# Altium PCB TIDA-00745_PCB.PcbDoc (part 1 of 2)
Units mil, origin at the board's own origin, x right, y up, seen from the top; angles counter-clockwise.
Board outline 7745 x 3490 mil, 4 copper layers (Top Layer, Signal Layer 1, Signal Layer 2, Bottom Layer), stack 61.2 mil thick; 181 components, 60 nets, 404 pads, 89 vias.
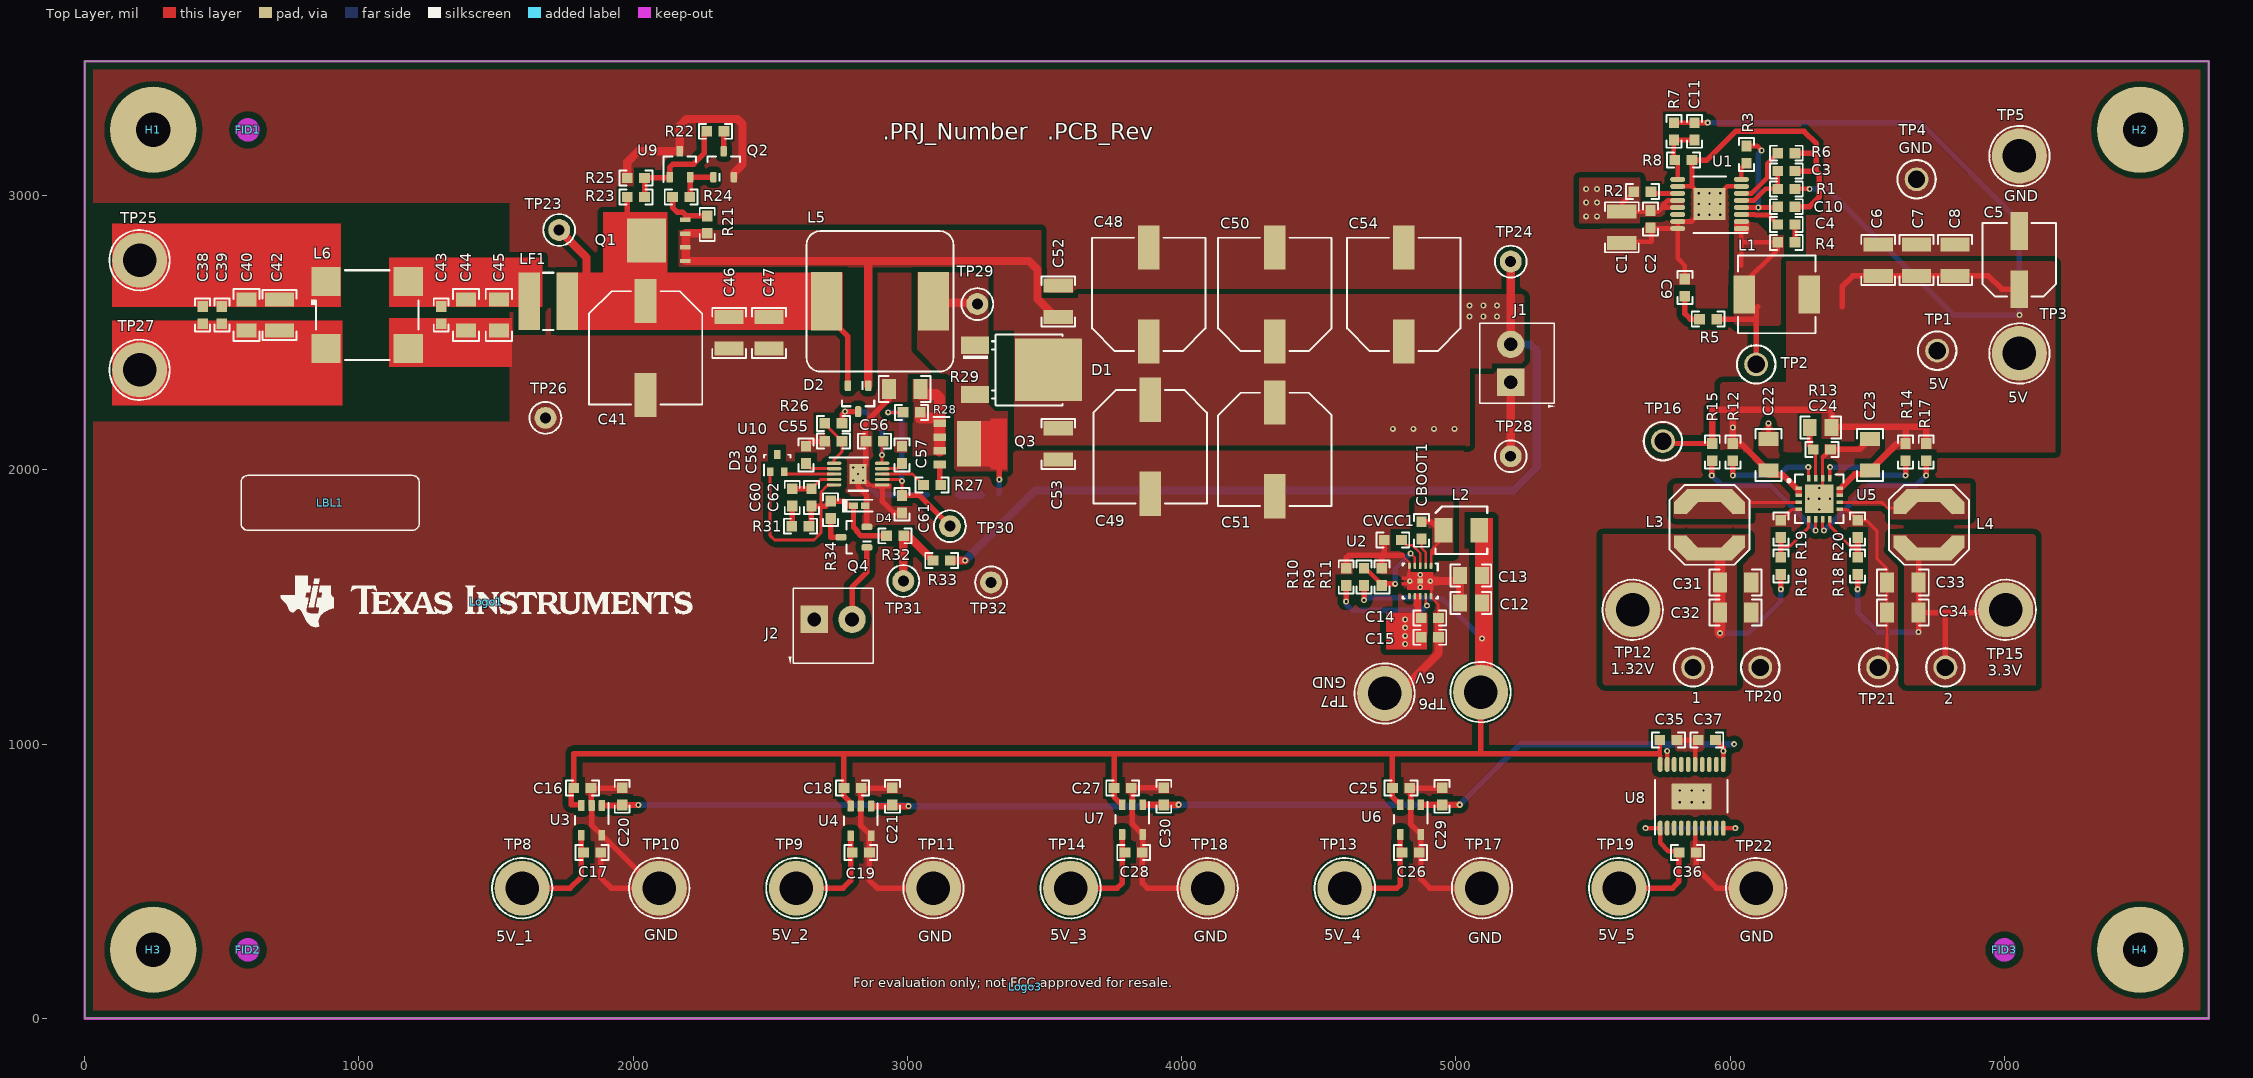
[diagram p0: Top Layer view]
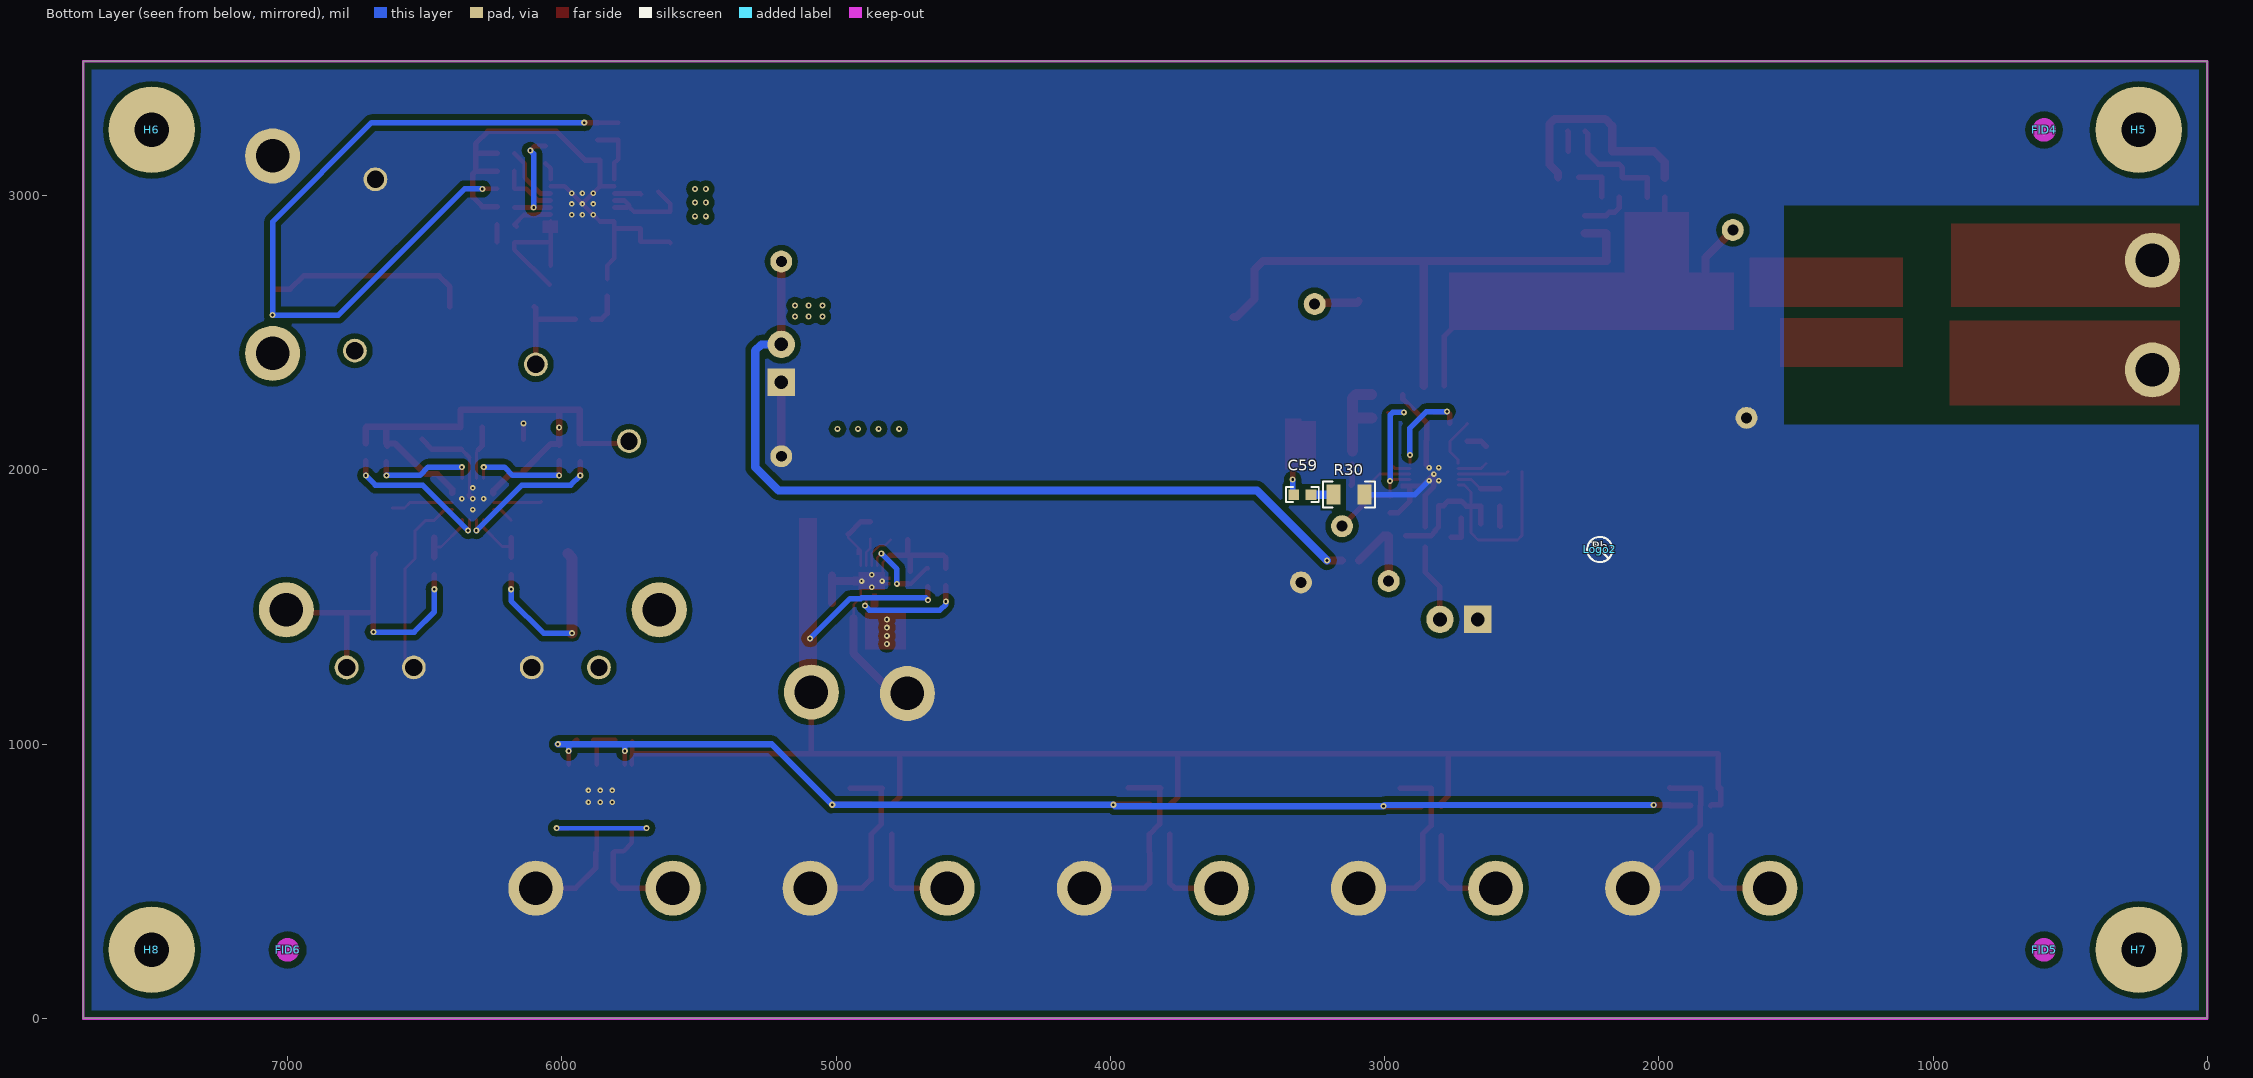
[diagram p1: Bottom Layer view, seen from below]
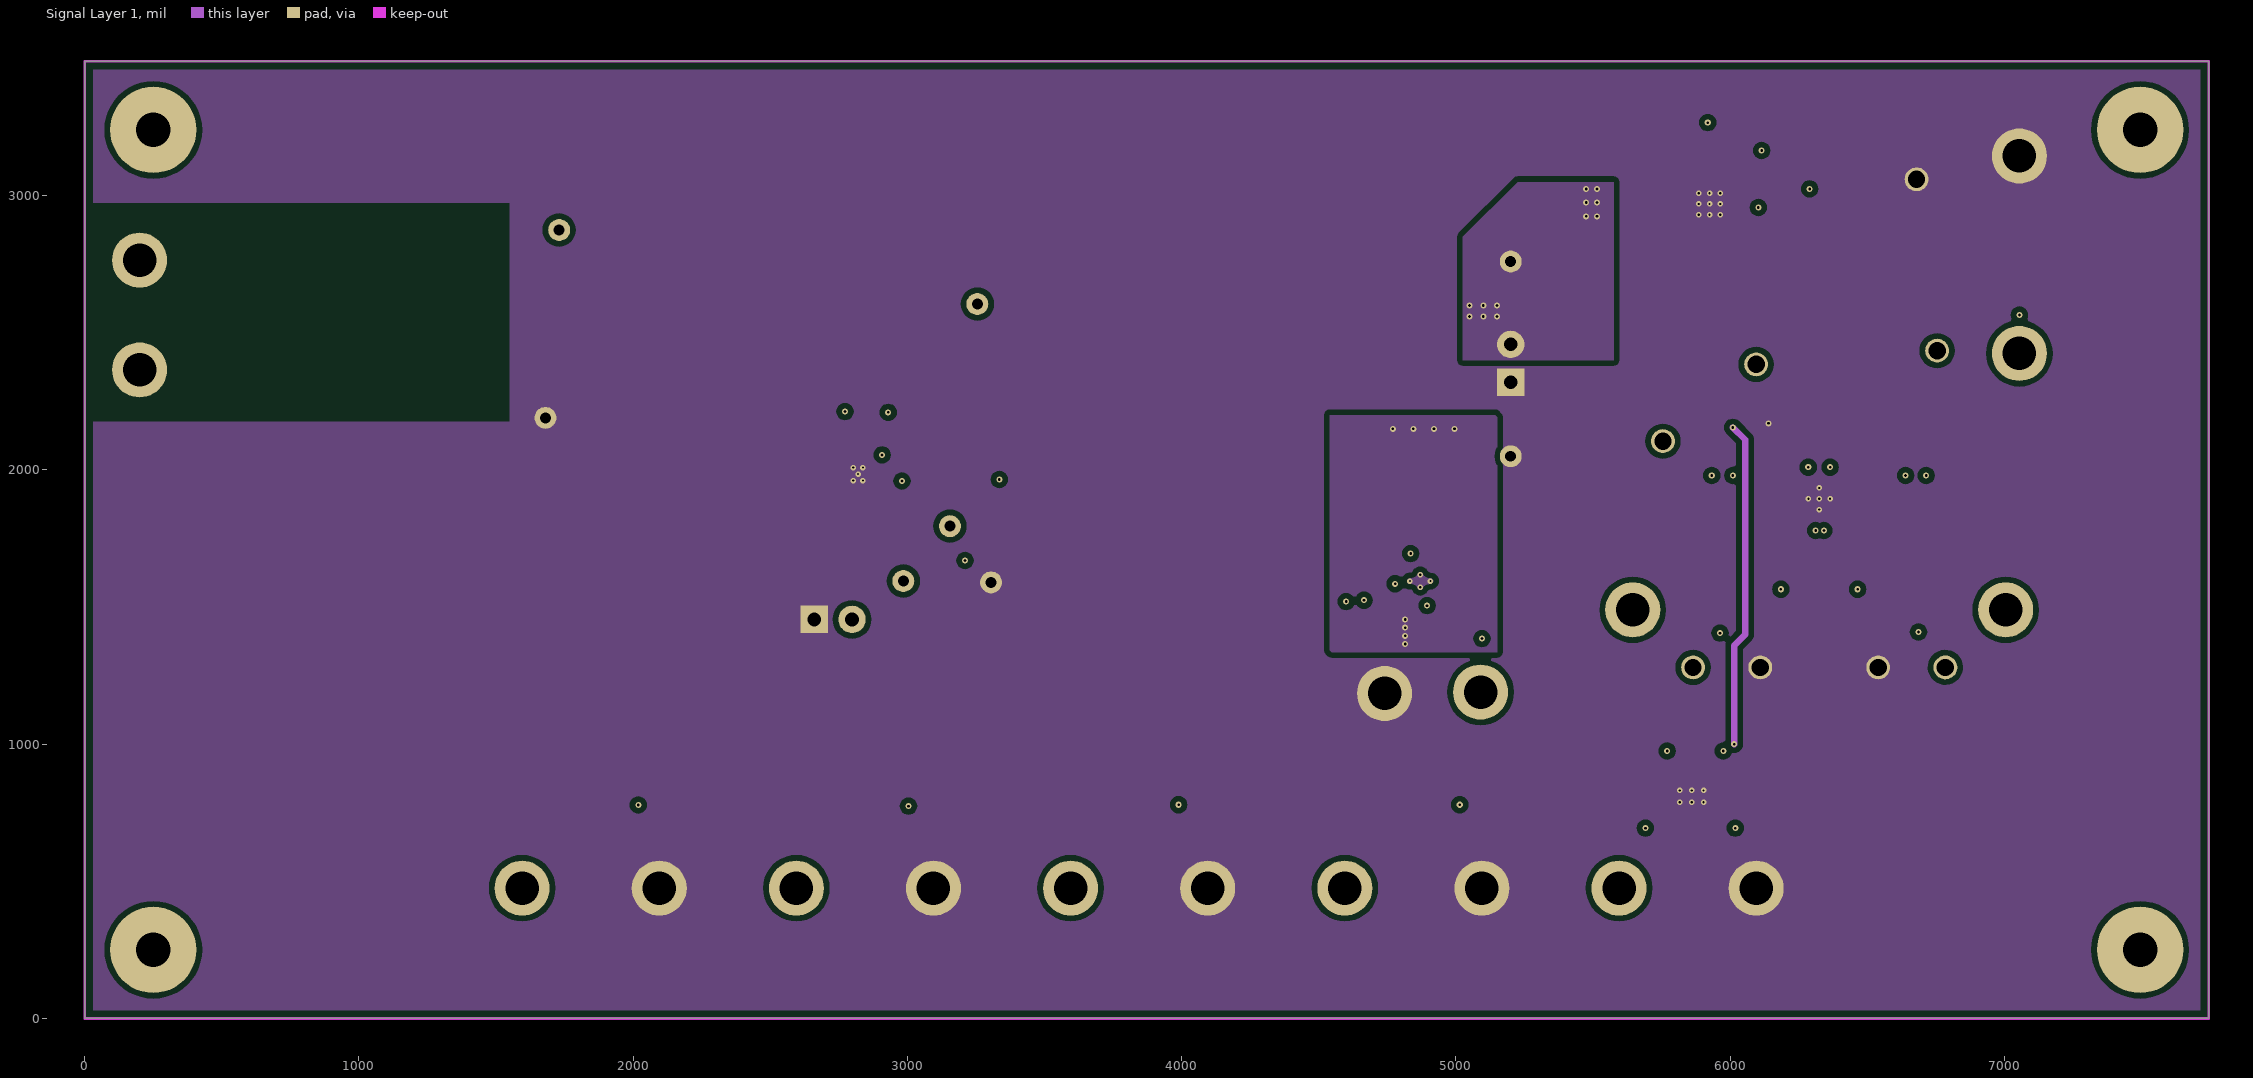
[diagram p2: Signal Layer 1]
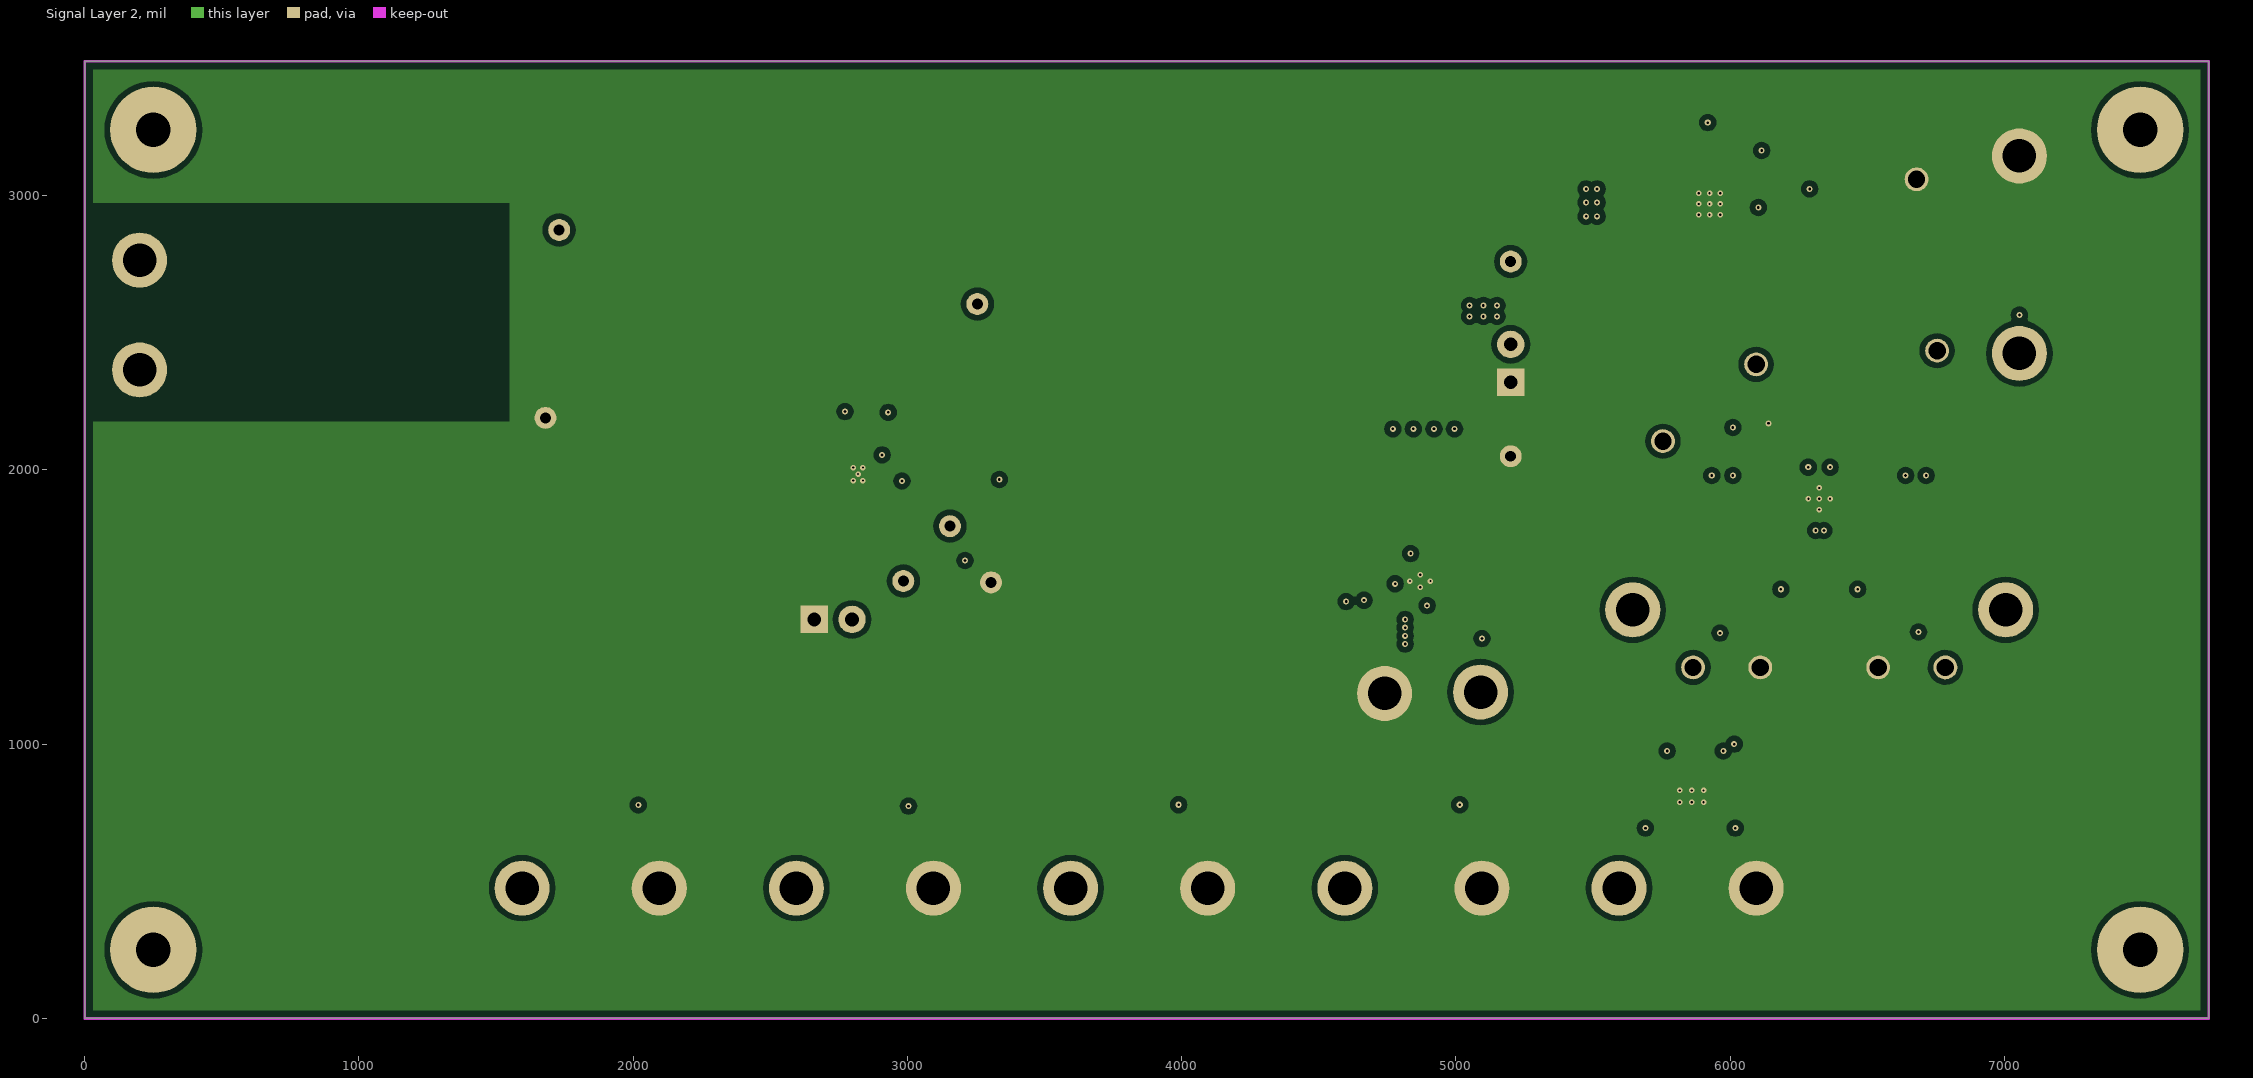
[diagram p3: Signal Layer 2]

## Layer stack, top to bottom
Top Layer: signal copper 1.4
Dielectric: core 26, FR-4, Dk 4.2
Signal Layer 1: signal copper 0.7
Dielectric: prepreg 5, Dk 4.2
Signal Layer 2: signal copper 0.7
Dielectric: core 26, Dk 4.2
Bottom Layer: signal copper 1.4

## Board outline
0,0 0,3490 7745,3490 7745,0

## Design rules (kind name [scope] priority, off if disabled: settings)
AcuteAngle [All] p1: minimum=4.50000000000000E+0001 checktracksonly=FALSE
AssemblyTestPointUsage [All] p1: valid=2
Clearance Clearance_Keepouts [((IsTrack Or IsArc) And Not InPoly) And IsFree and IsKeepOut vs ((IsTrack Or IsArc) And Not InPoly) And IsFree and IsKeepOut] p1: gap=0
Clearance Clearance_BoardEdge_MountingHoles [OnCopper and InComponentClass('Mounting Holes') vs IsKeepOut] p2: gap=40
Clearance Clearance_BoardEdge_Poly [OnCopper and InPoly vs IsKeepOut] p3: gap=25
Clearance Clearance_BoardEdge [OnCopper and Not InComponentClass('Logo') and not InComponentClass('FiducialMark') and not InRegion(1000,500,4000,800) and Not IsKeepout vs IsKeepOut] p4: gap=75
Clearance Clearance_Poly [InPolygon] p5: gap=20
Clearance [All] p6: gap=7.87
ComponentClearance ComponentClearance_MountingHoles_FiducialMarks [InComponentClass('Mounting Holes') vs InComponentClass('FiducialMark')] p1: gap=50 collisioncheckmode=3 verticalgap=10 showdistances=FALSE
ComponentClearance ComponentClearance_Shunt [InComponentClass('Header') vs InComponentClass('Shunt')] p2: gap=0 collisioncheckmode=3 verticalgap=0 showdistances=FALSE
ComponentClearance ComponentClearance_Logo [InComponentClass('Logo')] p3: gap=50 collisioncheckmode=3 verticalgap=10 showdistances=FALSE
ComponentClearance ComponentClearance_ScrewToNut [(HasFootprint('NY PMS 440 0025 PH')) vs (HasFootprint('Keystone_1902C'))] p4: gap=5 collisioncheckmode=3 verticalgap=10 showdistances=FALSE
ComponentClearance ComponentClearance_MountingHoles [InComponentClass('Mounting Holes')] p5: gap=250 collisioncheckmode=3 verticalgap=100000 showdistances=FALSE
ComponentClearance ComponentClearance_SmallPassives [HasFootprint('0201*') or HasFootprint('0402*') or HasFootprint('0508') or HasFootprint('0603*') or HasFootprint('0612') or HasFootprint('0805*') or HasFootprint('0815*') or HasFootprint('0830*') or HasFootprint('1206*') or HasFootprint('1210*') or HasFootprint('1808*') or HasFootprint('1812*') or HasFootprint('1825*') or HasFootprint('2010*') or HasFootprint('2220*') or HasFootprint('2225*') or HasFootprint('2512*') or HasFootprint('2728*') or HasFootprint('3518*') vs HasFootprint('0201*') or HasFootprint('0402*') or HasFootprint('0508') or HasFootprint('0603*') or HasFootprint('0612') or HasFootprint('0805*') or HasFootprint('0815*') or HasFootprint('0830*') or HasFootprint('1206*') or HasFootprint('1210*') or HasFootprint('1808*') or HasFootprint('1812*') or HasFootprint('1825*') or HasFootprint('2010*') or HasFootprint('2220*') or HasFootprint('2225*') or HasFootprint('2512*') or HasFootprint('2728*') or HasFootprint('3518*')] p6: gap=20 collisioncheckmode=3 verticalgap=10 showdistances=FALSE
ComponentClearance ComponentClearance_THtoSMT [IsThruComponent vs IsSMTComponent] p7: gap=100 collisioncheckmode=3 verticalgap=30 showdistances=FALSE
ComponentClearance ComponentClearance_THtoTH [IsThruComponent vs IsThruComponent] p8: gap=118.11 collisioncheckmode=3 verticalgap=30 showdistances=FALSE
ComponentClearance [All] p9: gap=40 collisioncheckmode=3 verticalgap=10 showdistances=FALSE
DiffPairsRouting [All] p1: maxlimit=100 minlimit=10 mostfreqgap=10 maxuncoupledlength=1000
FabricationTestPointUsage TestPointUsage [All] p1: valid=2 allowmultiple=FALSE
FabricationTestpoint Testpoint [All] p1: side=3 testpointundercomponent=TRUE minsize=40 maxsize=100 preferedsize=60 minholesize=0 maxholesize=40 preferedholesize=32 testpointgrid=1 allowsidetop=TRUE allowsidebottom=TRUE usegrid=TRUE gridtolerance=0.01
FanoutControl Fanout_LCC [IsLCC] p1: bgadir=Out bgaviamode=Centered fanoutstyle=Auto fanoutdirection=Alternating viagrid=1 // Fanout_LCC (Default Rule)
FanoutControl Fanout_BGA [IsBGA] p2: bgadir=Out bgaviamode=Centered fanoutstyle=Auto fanoutdirection=Alternating viagrid=1 // Fanout_BGA (Default Rule)
FanoutControl Fanout_Default [All] p4: bgadir=Out bgaviamode=Centered fanoutstyle=Auto fanoutdirection=Alternating viagrid=1 // Fanout_Default (Default Rule)
FanoutControl Fanout_Small [(CompPinCount < 5)] p5: bgadir=Out bgaviamode=Centered fanoutstyle=Auto fanoutdirection=OutThenIn viagrid=1 // Fanout_Small (Default Rule)
HoleSize [All] p1: absolutevalues=TRUE maxlimit=251 minlimit=8 maxpercent=80.000 minpercent=20.000
MinimumAnnularRing MinimumAnnularRing_ThermalPadVias [IsVia and InAnyComponent] p1: minimumring=6
MinimumAnnularRing [All] p2: minimumring=6
MinimumSolderMaskSliver MinimumSolderMaskSliver_Logo [InComponentClass('Logo') vs InComponentClass('Logo')] p1: minsoldermaskwidth=0.7
MinimumSolderMaskSliver [All] p2: minsoldermaskwidth=3.94
PlaneConnect [All] p1: planeconnectstyle=Relief reliefexpansion=10 reliefentries=4 reliefconductorwidth=10 reliefairgap=10
PolygonConnect [All] p1: connectstyle=Direct reliefconductorwidth=10 reliefentries=4 polygonreliefangle="90 Angle" airgapwidth=10
RoutingVias ThermalPadVias [IsVia and InAnyComponent] p1: holewidth=8 width=20 viastyle="Through Hole" minholewidth=8 minwidth=20 maxholewidth=12.99 maxwidth=23.62
RoutingVias [All] p2: holewidth=16 width=34 viastyle="Through Hole" minholewidth=8 minwidth=20 maxholewidth=40 maxwidth=65
SilkToSilkClearance SilkToSilkClearance_Pb-FreeLogo [(HasFootprint('Pb-Free_Overlay_Medium') OR HasFootprint('Pb-Free_Overlay_Small')) vs (HasFootprint('Pb-Free_Overlay_Medium') OR HasFootprint('Pb-Free_Overlay_Small'))] p1: silktosilkclearance=0
SilkToSilkClearance [All] p2: silktosilkclearance=4
SilkscreenOverComponentPads SilkToComonentPadClearance [IsPad and InAnycomponent] p1: minsilkscreentomaskgap=5
SilkscreenOverComponentPads "Silk to Solder Mask Opening" [All] p2: minsilkscreentomaskgap=4
SolderMaskExpansion [All] p1: expansion=1.97
Width [All] p1: maxlimit=100 minlimit=6 preferedwidth=10 checkconnectedcopper=TRUE
14 further rules are at their usual default settings.

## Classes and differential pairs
component class "TIDA-00745_Buck REV1": 1 2 C1 C2 C3 C4 C5 C6 C7 C8 C9 C10 C11 C12 C13 C14 C15 C16 C17 C18 C19 C20 C21 C22 C23 C24 C25 C26 C27 C28 C29 C30 C31 C32 C33 C34 C35 C36 C37 CBOOT1 CVCC1 L1 L2 L3 L4 R1 R2 R3 R4 R5 R6 R7 R8 R9 R10 R11 R12 R13 R14 R15 R16 R17 R18 R19 R20 TP1 TP2 TP3 TP4 TP5 TP6 TP7 TP8 TP9 TP10 TP11 TP12 TP13 TP14 TP15 TP16 TP17 TP18 TP19 TP20 TP21 TP22 U1 U2 U3 U4 U5 U6 U7 U8
component class "TIDA-00745 REV1": C38 C39 C40 C41 C42 C43 C44 C45 C46 C47 C48 C49 C50 C51 C52 C53 C54 C55 C56 C57 C58 C59 C60 C61 C62 D1 D2 D3 D4 J1 J2 L5 L6 LF1 Q1 Q2 Q3 Q4 R21 R22 R23 R24 R25 R26 R27 R28 R29 R30 R31 R32 R33 R34 TP23 TP24 TP25 TP26 TP27 TP28 TP29 TP30 TP31 TP32 U9 U10
component class Label: LBL1
component class "Mounting Holes": H1 H2 H3 H4
component class Logo: Logo1
component class TIDA-00745_Hardware: FID1 FID2 FID3 FID4 FID5 FID6 H1 H2 H3 H4 H5 H6 H7 H8 LBL1 Logo1 Logo2 Logo3 ZZ1 ZZ2 ZZ3 ZZ4
component class FiducialMark: FID1 FID2 FID3 FID4 FID5 FID6
component class AssemblyNote: ZZ1 ZZ2 ZZ3 ZZ4

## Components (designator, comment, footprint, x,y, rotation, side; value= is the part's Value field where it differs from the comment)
1 "5010" Keystone5010 5865,1280 r0 top
2 "5010" Keystone5010 6785,1280 r3 top
C1 "GRM32ER71H106KA12L" 1210 5605,2885 r270 top
C2 "06035C104KAT2A" 0603 5710,2915 r270 top
C3 "06035C104KAT2A" 0603 6205,3090 r0 top
C4 "C0603C474K8RACTU" 0603 6205,2895 r180 top
C5 "APXC6R3ARA181MF60G" CAPSMT_62_F60 7055,2765 r90 top
C6 "C3225X7R1C226M" 1210 6540,2765 r90 top
C7 "C3225X7R1C226M" 1210 6680,2765 r90 top
C8 "C3225X7R1C226M" 1210 6820,2765 r90 top
C9 "06031C102JAT2A" 0603 5835,2665 r90 top
C10 "GRM188R71A225KE15D" 0603 6205,2960 r0 top
C11 "GRM188R71E333KA01D" 0603 5870,3235 r270 top
C12 "C2012X7R1A106K125AC" 0805_HV 5055,1515 r180 top
C13 "C2012X7R1A106K125AC" 0805_HV 5055,1615 r180 top
C14 "GRM188R61C475KAAJ" 0603 4905,1460 r180 top
C15 "0603YC104JAT2A" 0603 4905,1390 r180 top
C16 "GRM188R71A105KA61D" 0603 1815,840 r0 top
C17 "GRM188R71A225KE15D" 0603 1850,605 r0 top
C18 "GRM188R71A105KA61D" 0603 2800,840 r0 top
C19 "GRM188R71A225KE15D" 0603 2830,605 r0 top
C20 "0603ZC103KAT2A" 0603 1960,810 r90 top
C21 "0603ZC103KAT2A" 0603 2945,810 r90 top
C22 "GRM31CR71A106KA01L" 1206 6140,2055 r90 top
C23 "GRM31CR71A106KA01L" 1206 6510,2055 r90 top
C24 "GRM188R71A474KA61D" 0603 6335,2075 r0 top
C25 "GRM188R71A105KA61D" 0603 4800,840 r0 top
C26 "GRM188R71A225KE15D" 0603 4835,605 r0 top
C27 "GRM188R71A105KA61D" 0603 3785,840 r0 top
C28 "GRM188R71A225KE15D" 0603 3825,605 r0 top
C29 "0603ZC103KAT2A" 0603 4950,810 r90 top
C30 "0603ZC103KAT2A" 0603 3935,810 r90 top
C31 "GRM31CR60J476ME19L" 1206 6020,1590 r0 top
C32 "GRM31CR71A226KE15L" 1206 6020,1480 r0 top
C33 "GRM31CR60J476ME19L" 1206 6630,1590 r180 top
C34 "GRM31CR71A226KE15L" 1206 6630,1480 r180 top
C35 "GRM188R71A105KA61D" 0603 5775,1015 r0 top
C36 "GRM188R71A225KE15D" 0603 5845,605 r0 top
C37 "0603ZC103KAT2A" 0603 5915,1015 r180 top
C38 "06031C102KAT2A" 0603 430,2565 r270 top
C39 "GRM188R72A104KA35D" 0603 500,2565 r270 top
C40 "C3216X7R2A105M160AA" 1206 590,2565 r270 top
C41 "EEE-FC1H470P" SM_RADIAL_G 2045,2445 r270 top
C42 "GRM32ER71H106KA12L" 1210 710,2565 r270 top
C43 "C1608X7R1H104K" 0603 1300,2565 r270 top
C44 "GRM31CR71H475KA12L" 1206 1390,2565 r270 top
C45 "GRM31CR71H475KA12L" 1206 1510,2565 r270 top
C46 "GRM32ER71H475KA88L" 1210 2350,2500 r270 top
C47 "GRM32ER71H475KA88L" 1210 2495,2500 r270 top
C48 "EEE-FC1H470P" SM_RADIAL_G 3880,2640 r90 top
C49 "EEE-FC1H470P" SM_RADIAL_G 3885,2085 r270 top
C50 "EEE-FC1H470P" SM_RADIAL_G 4340,2640 r90 top
C51 "EEE-FC1H470P" SM_RADIAL_G 4340,2075 r270 top
C52 "GRM32ER71H475KA88L" 1210 3550,2615 r90 top
C53 "GRM32ER71H475KA88L" 1210 3550,2095 r270 top
C54 "EEE-FC1H470P" SM_RADIAL_G 4810,2640 r90 top
C55 "06035A101JAT2A" 0603 2730,2105 r0 top
C56 "GRM188R71H104KA93D" 0603 2880,2105 r180 top
C57 "GRM188R71E105KA12D" 0603 2980,2055 r90 top
C58 "GRM188R71H333KA61D" 0603 2630,2055 r90 top
C59 "GRM188R71E222KA01D" 0603 3300,1910 r180 bottom
C60 "C0603C561K5RACTU" 0603 2580,1900 r270 top
C61 "GRM188R71H331KA01D" 0603 2980,1875 r270 top
C62 "06035A101JAT2A" 0603 2650,1900 r90 top
CBOOT1 "GRM188R71H104KA93D" 0603 4875,1780 r90 top
CVCC1 "C1608X7R1C105K" 0603 4770,1745 r0 top
D1 "12CWQ06FNPBF" DPAK 3380,2365 r0 top
D2 "BAS70-05-7-F" SOT-23 2820,2260 r270 top
D3 "BAV99WT1G" SOT-323 2525,2025 r90 top
D4 "BZT52C8V2T-7" SOD-523 2825,1870 r0 top
FID1 "Fiducial" Fiducial10-20 595,3240 r0 top
FID2 "Fiducial" Fiducial10-20 595,250 r0 top
FID3 "Fiducial" Fiducial10-20 7000,250 r0 top
FID4 "Fiducial" Fiducial10-20 595,3240 r180 bottom
FID5 "Fiducial" Fiducial10-20 595,250 r180 bottom
FID6 "Fiducial" Fiducial10-20 7000,250 r180 bottom
H1 "NY PMS 440 0025 PH" "NY PMS 440 0025 PH" 250,3240 r0 top locked
H2 "NY PMS 440 0025 PH" "NY PMS 440 0025 PH" 7495,3240 r0 top locked
H3 "NY PMS 440 0025 PH" "NY PMS 440 0025 PH" 250,250 r0 top locked
H4 "NY PMS 440 0025 PH" "NY PMS 440 0025 PH" 7495,250 r0 top locked
H5 "1902C" Keystone_1902C 250,3240 r180 bottom locked
H6 "1902C" Keystone_1902C 7495,3240 r180 bottom locked
H7 "1902C" Keystone_1902C 250,250 r180 bottom locked
H8 "1902C" Keystone_1902C 7495,250 r180 bottom locked
J1 "ED555/2DS" TERM_BLK_ED555-2DS 5200,2320 r90 top
J2 "ED555/2DS" TERM_BLK_ED555-2DS 2660,1455 r0 top
L1 "FDV0630-2R2M" IND_FDV0630 6170,2640 r0 top
L2 "MPI4040R3-4R7-R" MPI4040R3 5020,1780 r0 top
L3 "LPS6225-332MLB" LPS6225 5925,1800 r90 top
L4 "LPS6225-332MLB" LPS6225 6725,1800 r270 top
L5 "744771003" WE-PD-L 2900,2615 r0 top
L6 "744273102" WE-SL5_HC 1030,2565 r0 top
LBL1 "Size: 0.65\" x 0.20 \"" Label_650x200 895,1880 r0 top
LF1 "74408943022" WE-SPC_4838 1690,2615 r0 top
Logo1 "Texas Instruments" TI_Horizontal_Overlay_Medium 1465,1520 r0 top
Logo2 "Pb-Free Symbol" Pb-Free_Overlay_Small 2215,1710 r180 bottom
Logo3 "FCC disclaimer" FCC_disclaimer 3430,115 r0 top
Q1 "SQJ461EP" PowerPAK_SO-8L 2079.68,2837 r180 top
Q2 "SI2308BDS-T1-E3" SOT-23 2330,3115 r90 top
Q3 "BUK9Y9R0-60E" LFPAK56 3225,2095 r270 top
Q4 "2N7002-7-F" SOT-23 2805,1755 r180 top
R1 "CRCW06030000Z0EA" 0603 6205,3025 r0 top
R2 "CRCW06030000Z0EA" 0603 5680,3015 r180 top
R3 "CRCW0603100KFKEA" 0603 6060,3150 r90 top
R4 "CRCW06030000Z0EA" 0603 6205,2830 r180 top
R5 "CRCW06034R99FKEA" 0603 5920,2550 r0 top
R6 "CRCW0603100KFKEA" 0603 6205,3155 r180 top
R7 "CRCW06030000Z0EA" 0603 5795,3235 r90 top
R8 "DNP" 0603 5830,3130 r180 top
R9 "RT0603BRD0750K5L" 0603 4665,1610 r270 top
R10 "CRCW0603100KFKEA" 0603 4600,1610 r270 top
R11 "RT0603BRD0710KL" 0603 4730,1610 r270 top
R12 "RC0603JR-0710KL" 0603 6010,2065 r90 top
R13 "RC0805FR-074R99L" 0805_HV 6330,2155 r0 top
R14 "RC0603JR-0710KL" 0603 6640,2065 r90 top
R15 "CRCW060349K9FKEA" 0603 5935,2065 r270 top
R16 "RT0603BRD076K65L" 0603 6185,1650 r270 top
R17 "CRCW060349K9FKEA" 0603 6715,2065 r270 top
R18 "RT0603BRD0731K6L" 0603 6465,1650 r270 top
R19 "RT0603BRD0710K2L" 0603 6185,1785 r270 top
R20 "RT0603BRD0710K2L" 0603 6465,1785 r270 top
R21 "RC0603JR-072K2L" 0603 2270,2895 r270 top
R22 "CRCW06031M50JNEA" 0603 2300,3235 r180 top
R23 "CRCW0603215KFKEA" 0603 2010,2995 r180 top
R24 "RG1608P-332-B-T5" 0603 2175,2995 r180 top
R25 "CRCW0603100KFKEA" 0603 2010,3065 r0 top
R26 "RC0603FR-07357KL" 0603 2730,2170 r0 top
R27 "CRCW06030000Z0EA" 0603 3090,1945 r0 top
R28 "CRCW06031K00JNEA" 0603 3015,2210 r0 top
R29 "CSR1206FK12L0" 1206 2990,2295 r0 top
R30 "RC1206FR-071R8L" 1206 3130,1910 r0 bottom
R31 "CRCW0603121KFKEA" 0603 2610,1795 r180 top
R32 "CRCW060351K1FKEA" 0603 2955,1760 r0 top
R33 "CRCW060349R9FKEA" 0603 3125,1670 r0 top
R34 "CRCW06035K23FKEA" 0603 2720,1855 r90 top
TP1 "5V" Keystone5010 6755,2435 r0 top
TP2 "SW" Keystone5012 6095,2385 r0 top
TP3 "5V" Keystone1503-2 7055,2425 r0 top
TP4 "GND" Keystone5011 6680,3060 r0 top
TP5 "GND" Keystone1503-2 7055,3145 r0 top
TP6 "6V" Keystone1503-2 5090,1190 r0 top
TP7 "GND" Keystone1503-2 4740,1185 r0 top
TP8 "5V_1" Keystone1503-2 1595,475 r0 top
TP9 "5V_2" Keystone1503-2 2595,475 r0 top
TP10 "GND" Keystone1503-2 2095,475 r0 top
TP11 "GND" Keystone1503-2 3095,475 r0 top
TP12 "1.32V" Keystone1503-2 5645,1490 r0 top
TP13 "5V_4" Keystone1503-2 4595,475 r0 top
TP14 "5V_3" Keystone1503-2 3595,475 r0 top
TP15 "3.3V" Keystone1503-2 7005,1490 r0 top
TP16 "3.3V" Keystone5010 5755,2105 r0 top
TP17 "GND" Keystone1503-2 5095,475 r0 top
TP18 "GND" Keystone1503-2 4095,475 r0 top
TP19 "5V_5" Keystone1503-2 5595,475 r0 top
TP20 "5011" Keystone5011 6110,1280 r0 top
TP21 "5011" Keystone5011 6540,1280 r0 top
TP22 "GND" Keystone1503-2 6095,475 r0 top
TP23 "5000" Keystone5000 1730,2875 r0 top
TP24 "5000" Keystone5000 5200,2760 r0 top
TP25 "BAT+" Keystone1503-2 200,2765 r0 top
TP26 "5001" Keystone5001 1680,2190 r0 top
TP27 "BAT-" Keystone1503-2 200,2365 r0 top
TP28 "5001" Keystone5001 5200,2050 r0 top
TP29 "5002" Keystone5002 3255,2605 r0 top
TP30 "5002" Keystone5002 3155,1795 r0 top
TP31 "5003" Keystone5003 2985,1595 r0 top
TP32 "5001" Keystone5001 3305,1590 r0 top
U1 "LM536025QPWP" PWP0016A_N 5925,2970 r180 top
U2 "LM53600NQDSXRQ1" DSX0010A 4870,1595 r270 top
U3 "TPS7B4250QDBVRQ1" DBV0005A_N 1848.45,722.15 r270 top
U4 "TPS7B4250QDBVRQ1" DBV0005A_N 2830,720 r270 top
U5 "LM26420XSQ/NOPB" SQB16A 6325,1895 r0 top
U6 "TPS7B4250QDBVRQ1" DBV0005A_N 4835,725 r270 top
U7 "TPS7B4250QDBVRQ1" DBV0005A_N 3820,725 r270 top
U8 "TPS7B4253QPWPRQ1" PWP0020D_N 5860,810 r90 top
U9 "TLVH431BQDBZRQ1" DBZ0003A_N 2170,3115 r90 top
U10 "TPS40210DGQ" DGQ0010D_N 2820,1985 r0 top
ZZ1 "This Assembly Note is for PCB labels only" AssemblyNoteLabel 400,5265 r0 top
ZZ2 "These assemblies are ESD sensitive, ESD precautions shall be observed." AssemblyNote 400,5115 r0 top
ZZ3 "These assemblies must be clean and free from flux and all contaminants. Use of no clean flux is not acceptable." AssemblyNote 400,4965 r0 top
ZZ4 "These assemblies must comply with workmanship standards IPC-A-610 Class 2, unless otherwise specified." AssemblyNote 400,4815 r0 top

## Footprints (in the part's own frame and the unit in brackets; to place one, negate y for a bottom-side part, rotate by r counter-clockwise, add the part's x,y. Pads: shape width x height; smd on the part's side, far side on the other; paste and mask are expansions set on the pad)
0603 [mm] "0603 from SM-752 data"
  rect 1x0.95 smd: 1(-0.8,0) 2(0.8,0)
  silkscreen extent -1.52,-0.69 1.52,0.69, body extent -0.87,-0.47 0.87,0.47, height 1
0805_HV [mil] "0805 with 30mil clearance between pads"
  rect 50x63 smd: 1(-40,0) 2(40,0)
  silkscreen extent -74,-40 74,40, body extent -43,-29 43,29, height 57
1206 [mm] "1206 from SM-752 data"
  rect 1.3x1.85 smd: 1(-1.45,0) 2(1.45,0)
  silkscreen extent -2.4,-1.21 2.4,1.21, body extent -1.7,-0.9 1.7,0.9, height 1.35
1210 [mm] "1210 from SM-752 data"
  rect 1.3x2.7 smd: 1(-1.45,0) 2(1.45,0)
  silkscreen extent -2.32,-1.57 2.32,1.57, body extent -1.7,-1.35 1.7,1.35, height 1.35
AssemblyNote [mil] "Assembly Note"
AssemblyNoteLabel [mil] "Assembly Note for PCB Labels"
CAPSMT_62_F60 [mm] "6.3 x 5.7mm:  Chemi-Con F60"
  rect 3.5x1.6 smd: 1(-2.688,0.012) 2(2.712,0.012)
  silkscreen extent -3.35,-3.39 3.45,3.41, body extent -3.4,-3.4 3.45,3.42, height 6
DBV0005A_N [mm] "SOT23, 5-Leads, Body 2.9x1.6mm, Pitch 0.95mm, Lead Span 2.8mm, IPC Medium Density"
  rrect17% 1x0.6 smd: 1(-1.375,0.95) 2(-1.375,0) 3(-1.375,-0.95) 4(1.375,-0.95) 5(1.375,0.95)
  silkscreen extent -1.63,-1.55 0.38,1.55, body extent -1.42,-1.46 1.42,1.46, height 1.09
DBZ0003A_N [mm] "SOT23, 3-Leads, Body 2.9x1.3mm, Pitch 0.95mm, Lead Span 2.4mm, IPC Medium Density"
  rrect17% 1x0.6 smd: 1(-1.2,0.95) 2(-1.2,-0.95) 3(1.2,0)
  silkscreen extent -1.65,-1.5 0.7,1.5, body extent -1.26,-1.46 1.26,1.46, height 0.98
DGQ0010D_N [mm] "TSSOP, 10-Leads, Body 3x3mm, Pitch 0.5mm, Thermal Pad 1.88x1.57mm, IPC Medium Density"
  rrect100% 1.35x0.3 smd: 1(-2.225,1) 2(-2.225,0.5) 3(-2.225,0) 4(-2.225,-0.5) 5(-2.225,-1) 6(2.225,-1) 7(2.225,-0.5) 8(2.225,0) 9(2.225,0.5) 10(2.225,1)
  rrect6% 1.57x1.88 smd: 11(0,0)
  silkscreen extent -2.65,-1.55 0.9,1.55, body extent -2.46,-1.5 2.46,1.5, height 1.1
DPAK [mm] "D-PAK, 3-Pads, Body 6.22x6.73mm (max), TO-252AA using nominal STEP model"
  rrect6% 2.6x1.6 smd: 1(-3.4,2.28) 3(-3.4,-2.28)
  rrect2% 6.2x5.8 smd paste-2.9: 4(3.4,0)
  silkscreen extent -4.5,-3.3 4.7,3.28, body extent -3.86,-3.29 5.84,3.29, height 2.48
DSX0010A [mm] "SON, 10-Leads, Body 3x3 mm, Pitch 0.5mm"
  rrect100% 0.6x0.25 smd mask+0.07: 1(-1.4,1) 2(-1.4,0.5) 3(-1.4,0) 4(-1.4,-0.5) 5(-1.4,-1) 6(1.4,-1) 7(1.4,-0.5) 8(1.4,0) 9(1.4,0.5) 10(1.4,1)
  rrect20% 0.5x0.5 smd paste-0.5: 11(0,0)
  Top Layer region: -0.375,-1.7 -0.375,-1.2 -0.825,-1.2 -0.825,1.2 -0.375,1.2 -0.375,1.7 -0.125,1.7 -0.125,1.2 0.125,1.2 0.125,1.7 0.375,1.7 0.375,1.2 0.825,1.2 0.825,-1.2 0.375,-1.2 0.375,-1.7 0.125,-1.7 0.125,-1.2 -0.125,-1.2 -0.125,-1.7
  silkscreen extent -1.63,-1.63 1.63,1.63, body extent -1.53,-1.53 1.53,1.53, height 0.81
FCC_disclaimer [mil]
Fiducial10-20 [mm]
  round 1 smd mask+0.5: 1(0,0)
  Top Layer keep-out circle w1.178: c0,0 r0.5
IND_FDV0630 [mm] "TOKO"
  rect 2x3.5 smd: 1(-3,0) 2(3,0)
  silkscreen extent -3.6,-3.6 3.6,3.6, body extent -3.5,-3.5 3.5,3.5, height 3
Keystone1503-2 [mm] "Double Turret"
  round 5.1 hole 3.1: 1(0,0)
  silkscreen extent -2.79,-2.79 2.79,2.79, body extent -2.4,-2.4 2.38,2.4, height 9.22
Keystone5000 [mil] "For Keystone 500x miniature loop terminals"
  round 80 hole 40: 1(0,0)
  silkscreen extent -58,-58 58,58, body extent -49,-49 49,49, height 182
Keystone5001 [mil] "For Keystone 500x miniature loop terminals"
  round 80 hole 40: 1(0,0)
  silkscreen extent -58,-58 58,58, body extent -49,-49 49,49, height 182
Keystone5002 [mil] "For Keystone 500x miniature loop terminals"
  round 80 hole 40: 1(0,0)
  silkscreen extent -58,-58 58,58, body extent -49,-49 49,49, height 182
Keystone5003 [mil] "For Keystone 500x miniature loop terminals"
  round 80 hole 40: 1(0,0)
  silkscreen extent -58,-58 58,58, body extent -49,-49 49,49, height 182
Keystone5010 [mil] "Keystone Multipurpose loops"
  round 87 hole 63: 1(0,0)
  silkscreen extent -70,-70 70,70, body extent -63,-63 63,62, height 319
Keystone5011 [mil] "Keystone Multipurpose loops"
  round 87 hole 63: 1(0,0)
  silkscreen extent -70,-70 70,70, body extent -63,-63 63,62, height 319
Keystone5012 [mil] "Keystone Multipurpose loops"
  round 87 hole 63: 1(0,0)
  silkscreen extent -70,-70 70,70, body extent -63,-63 63,62, height 319
Keystone_1902C [mil] "Hex Standoff, 4-40 threaded, nylon"
  body extent -145,-126 146,126, height 501
Label_650x200 [mil] "Thermal Transfer Label"
  round 1 on Mech13: 0(0,0)
  silkscreen extent -325,-100 325,100, body extent -326,-101 326,101, height 1
LFPAK56 [mm] "NXP Semiconductor"
  rect 0.7x1.15 smd paste-0.05: 1(-1.905,-2.725) 2(-0.635,-2.725) 3(0.635,-2.725) 4(1.905,-2.725)
  rect 4.2x2.2 smd paste-1.52: 5(0,0)
  Top Layer region: -2.1,0.65 2.1,0.65 2.1,2 -2.1,2
  Top Layer region: -2.1,1.8 -2.1,2 -2.35,2 -2.35,3.5 2.35,3.5 2.35,2 2.1,2 2.1,1.8
  silkscreen extent -2.5,-3.3 -2.5,-1.8, body extent -2.43,-3.14 2.47,3.29, height 1.18
LPS6225 [mm] "Coilcraft recommended land pattern.  Document 554-2, rev 10/6/08"
  rect 1.2x4.25 smd: 1(-2.7,0) 2(2.7,0)
  rect 1.68x1.6 smd rot 135: 1(-2.126,-2.151) 2(2.126,2.151)
  rect 1.68x1.6 smd rot 45: 1(-2.126,2.151) 2(2.126,-2.151)
  rect 1.125x1.2 smd: 1(-1.562,2.7) 1(-1.562,-2.7) 2(1.562,2.7) 2(1.562,-2.7)
  silkscreen extent -3.7,-3.7 3.7,3.7, body extent -3.1,-3.1 3.1,3.1, height 2.52
MPI4040R3 [mm] "Coiltronics"
  rect 1.65x2.3 smd: 1(-1.65,0) 2(1.65,0)
  silkscreen extent -2.4,-2.2 2.4,2.2, body extent -2.35,-2.15 2.35,2.15, height 1.86
"NY PMS 440 0025 PH" [mm] "4-40 nylon screw and mounting hole"
  round 8 hole 3.2: 1(0,0)
  body extent -3.3,-3.3 3.3,3.3, height 2.69
Pb-Free_Overlay_Small [mil]
  silkscreen extent -46,-46 46,46
PowerPAK_SO-8L [mm] "based on Vishay recommended land pattern Document 63818 Feb 7, 2012"
  rect 1x0.41 smd: 1(-2.805,1.905) 2(-2.805,0.635) 3(-2.805,-0.635) 4(-2.805,-1.905)
  rect 3.63x4.061 smd: 5(0.805,0)
  Top Layer region: -0.297,-2.64 0.298,-2.64 0.298,-2.03 -0.297,-2.03
  Top Layer region: -0.298,2.03 0.297,2.03 0.297,2.64 -0.298,2.64
  Top Layer region: 2.615,-2.5 3.125,-2.5 3.125,2.5 2.615,2.5
  body extent -3.07,-2.57 3.08,2.57, height 1.21
PWP0016A_N [mm] "TSOP, 16-Leads, Body 5x4.4mm, Pitch 0.65mm, Exposed Pad, IPC Medium Density"
  rrect100% 1.4x0.45 smd: 1(-2.95,2.275) 2(-2.95,1.625) 3(-2.95,0.975) 4(-2.95,0.325) 5(-2.95,-0.325) 6(-2.95,-0.975) 7(-2.95,-1.625) 8(-2.95,-2.275) 9(2.95,-2.275) 10(2.95,-1.625) 11(2.95,-0.975) 12(2.95,-0.325) 13(2.95,0.325) 14(2.95,0.975) 15(2.95,1.625) 16(2.95,2.275)
  rrect3% 3x3 smd: 17(0,0)
  silkscreen extent -3.5,-2.55 1.5,2.7, body extent -3.21,-2.5 3.21,2.5, height 1
PWP0020D_N [mm] "SOP, 20-Leads, Body 6.4x4.4mm, Pitch 0.65mm, Thermal Pad 2x3mm, IPC Medium Density"
  rrect100% 1.4x0.45 smd: 1(-2.95,2.925) 2(-2.95,2.275) 3(-2.95,1.625) 4(-2.95,0.975) 5(-2.95,0.325) 6(-2.95,-0.325) 7(-2.95,-0.975) 8(-2.95,-1.625) 9(-2.95,-2.275) 10(-2.95,-2.925) 11(2.95,-2.925) 12(2.95,-2.275) 13(2.95,-1.625) 14(2.95,-0.975) 15(2.95,-0.325) 16(2.95,0.325) 17(2.95,0.975) 18(2.95,1.625) 19(2.95,2.275) 20(2.95,2.925)
  rrect4% 2.4x3.7 smd: 21(0,0)
  silkscreen extent -3.55,-3.3 1.5,3.4, body extent -3.21,-3.25 3.21,3.25, height 1
SM_RADIAL_G [mm] "10 x 10.2mm:  Panasonic G"
  rect 4.1x2 smd: 1(-4.35,0) 2(4.35,0)
  silkscreen extent -5.25,-5.25 5.25,5.25, body extent -5.26,-5.26 5.26,5.26, height 10.5
SOD-523 [mm] "NXP Semiconductor recommended land pattern, nominal STEP model"
  rect 0.8x0.6 smd paste-0.05: 1(-0.55,0) 2(0.55,0)
  silkscreen extent -1.6,-0.64 1.2,0.64, body extent -0.8,-0.4 0.8,0.4, height 0.72
SOT-23 [mm] "SOT23, 3-Leads, Body 2.9x1.3mm, Pitch 0.95mm, Lead Span 2.5mm, IPC Medium Density"
  rrect50% 1x0.6 smd: 1(-1.2,0.95) 2(-1.2,-0.95) 3(1.2,0)
  silkscreen extent -1.63,-1.5 0.7,1.5, body extent -1.16,-1.45 1.21,1.45, height 1
SOT-323 [mm] "Zetex recommended land pattern.  March 2007"
  rect 0.8x0.6 smd: 1(-0.8,0.65) 2(-0.8,-0.65) 3(0.8,0)
  silkscreen extent -1.14,-1.22 0.77,1.22, body extent -1.13,-1.13 1.12,1.12, height 1.13
SQB16A [mm] "QFN, 16-Leads, Body 4x4mm, Pitch 0.65mm, NSC Recommended"
  rect 0.6x0.3 smd paste-0.15 mask+0.051: 1(-1.9,0.975) 2(-1.9,0.325) 3(-1.9,-0.325) 4(-1.9,-0.975) 9(1.9,-0.975) 10(1.9,-0.325) 11(1.9,0.325) 12(1.9,0.975)
  rect 0.3x0.6 smd paste-0.15 mask+0.051: 5(-0.975,-1.9) 6(-0.325,-1.9) 7(0.325,-1.9) 8(0.975,-1.9) 13(0.975,1.9) 14(0.325,1.9) 15(-0.325,1.9) 16(-0.975,1.9)
  rect 2.6x2.6 smd paste-1.3 mask+0.051: 17(0,0)
  silkscreen extent -2.92,-2.25 2.25,2.25, body extent -2.05,-2.05 2.05,2.05, height 0.8
TERM_BLK_ED555-2DS [mil]
  rect 100x100 hole 50: 1(0,0)
  round 100 hole 50: 2(138,0)
  silkscreen extent -93,-161 215,113, body extent -69,-150 207,106, height 323
TI_Horizontal_Overlay_Medium [mil]
  silkscreen extent -750,-94 750,94
WE-PD-L [mm] "Wurth Elektronik recommended land pattern, 2005-06-22"
  rect 2.9x5.4 smd: 1(-4.95,0) 2(4.95,0)
  silkscreen extent -6.8,-6.5 6.8,6.5, body extent -6.16,-6.19 6.16,6.14, height 6
WE-SL5_HC [mm] "SMD, 4-Leads, Body 9.5x8.3mm"
  rect 2.7x2.7 smd: 1(-3.8,3.1) 2(-3.8,-3.1) 3(3.8,-3.1) 4(3.8,3.1)
  silkscreen extent -5.2,-4.15 4.75,4.15, body extent -4.75,-4.15 4.75,4.15, height 5.31
WE-SPC_4838 [mm] "WURTH"
  rect 2x5.3 smd: 1(-1.75,0) 2(1.75,0)
  silkscreen extent -0.48,-2.65 0.48,2.65, body extent -2.55,-2.55 2.55,2.55, height 4.1

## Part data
1 2: "Test Point, Multipurpose, Red, TH"
C1 C42: "CAP, CERM, 10uF, 50V, +/-10%, X7R, 1210"
C2 C3 C43 C56 CBOOT1: "CAP, CERM, 0.1uF, 50V, +/-10%, X7R, 0603"
C4 C24: "CAP, CERM, 0.47uF, 10V, +/-10%, X7R, 0603"
C5: "CAP, AL, 180uF, 6.3V, +/-20%, 0.022 ohm, SMD"
C6 C7 C8: "CAP, CERM, 22uF, 16V, +/-20%, X7R, 1210"
C9: "CAP, CERM, 1000 pF, 100 V, +/- 5%, X7R, 0603"
C10: "CAP, CERM, 2.2uF, 10V, +/-10%, X7R, 0603"
C11: "CAP, CERM, 0.033uF, 25V, +/-10%, X7R, 0603"
C12 C13: "CAP, CERM, 10 µF, 10 V, +/- 10%, X7R, 0805"
C14: "CAP, CERM, 4.7 µF, 16 V, +/- 10%, X5R, 0603"
C15: "CAP, CERM, 0.1 µF, 16 V, +/- 5%, X7R, 0603"
C16 C18 C25 C27 C35: "CAP, CERM, 1 µF, 10 V, +/- 10%, X7R, 0603"
C17 C19 C26 C28 C36: "CAP, CERM, 2.2 µF, 10 V, +/- 10%, X7R, 0603"
C20 C21 C29 C30 C37: "CAP, CERM, 0.01 µF, 10 V, +/- 10%, X7R, 0603"
C22 C23: "CAP, CERM, 10uF, 10V, +/-10%, X5R, 1206"
C31 C33: "CAP, CERM, 47uF, 6.3V, +/-20%, X5R, 1206"
C32 C34: "CAP, CERM, 22uF, 10V, +/-10%, X7R, 1206"
C38: "CAP, CERM, 1000 pF, 100 V, +/- 10%, X7R, 0603"
C39: "CAP, CERM, 0.1uF, 100V, +/-10%, X7R, 0603"
C40: "CAP, CERM, 1uF, 100V, +/-20%, X7R, 1206"
C41 C48 C49 C50 C51 C54: "CAP, AL, 47 µF, 50 V, +/- 20%, 0.3 ohm, SMD"
C44 C45: "CAP, CERM, 4.7uF, 50V, +/-10%, X7R, 1206"
C46 C47 C52 C53: "CAP, CERM, 4.7 µF, 50 V, +/- 10%, X7R, 1210"
C55 C62: "CAP, CERM, 100 pF, 50 V, +/- 5%, C0G/NP0, 0603"
C57: "CAP, CERM, 1uF, 25V, +/-10%, X7R, 0603"
C58: "CAP, CERM, 0.033 µF, 50 V, +/- 10%, X7R, 0603"
C59: "CAP, CERM, 2200pF, 25V, +/-10%, X7R, 0603"
C60: "CAP, CERM, 560 pF, 50 V, +/- 10%, X7R, 0603"
C61: "CAP, CERM, 330pF, 50V, +/-10%, X7R, 0603"
CVCC1: "CAP, CERM, 1uF, 16V, +/-10%, X7R, 0603"
D1: "Diode, Schottky, 60 V, 12 A, DPAK"
D2: "Diode, Schottky, 70 V, 0.07 A, SOT-23"
D3: "Diode, P-N, 70 V, 0.2 A, SOT-323"
D4: "Diode, Zener, 8.2 V, 300 mW, SOD-523"
FID1 FID2 FID3 FID4 FID5 FID6: "Fiducial mark.  There is nothing to buy or mount."
H1 H2 H3 H4: "Machine Screw, Round, #4-40 x 1/4, Nylon, Philips panhead"
H5 H6 H7 H8: "Standoff, Hex, 0.5\"L #4-40 Nylon"
J1 J2: "Terminal Block, 6A, 3.5mm Pitch, 2-Pos, TH"
L1: "Inductor, Shielded, Powdered Iron, 2.2uH, 5.3A, 0.021 ohm, SMD"
L2: "Inductor, Shielded, ?, 4.7uH, 2.3A, 0.092 ohm, SMD"
L3 L4: "Inductor, Shielded Drum Core, Ferrite, 3.3uH, 1.35A, 0.05 ohm, SMD"
L5: "Inductor, Shielded Drum Core, Ferrite, 3.5 µH, 9 A, 0.005 ohm, SMD"
L6: "Coupled inductor, 11 µH, 2.5 A, 0.03 ohm, SMD"
LBL1: library part THT-14-423-10, "Thermal Transfer Printable Labels, 0.650\" W x 0.200\" H - 10,000 per roll"
LF1: "Inductor, Shielded Drum Core, Ferrite, 2.2 µH, 3 A, 0.026 ohm, SMD"
Logo1: library part TI_Logo, "Texas Instrument Corporate Signature"
Logo2: library part Pb-Free
Logo3: library part FCC_disclaimer, "FCC_disclaimer"
Q1: "MOSFET, P-CH, -60 V, 30 A, PowerPAK_SO-8L"
Q2: "MOSFET, N-CH, 60 V, 2.3 A, SOT-23"
Q3: library part BUK9Y3R5-40E,115, "MOSFET, N-CH, 60 V, 100 A, SOT669"
Q4: "MOSFET, N-CH, 60 V, 0.17 A, SOT-23"
R1 R2 R4 R7 R27: "RES, 0 ohm, 5%, 0.1W, 0603"
R3 R6 R10: "RES, 100k ohm, 1%, 0.1W, 0603"
R5: "RES, 4.99, 1%, 0.1 W, 0603"
R8: library part CRCW06034K99FKEA, "RES, 4.99k ohm, 1%, 0.1W, 0603"
R9: "RES, 50.5 k, 0.1%, 0.1 W, 0603"
R11: "RES, 10.0 k, 0.1%, 0.1 W, 0603"
R12 R14: "RES, 10k ohm, 5%, 0.1W, 0603"
R13: "RES, 4.99 ohm, 1%, 0.125W, 0805"
R15 R17: "RES, 49.9k ohm, 1%, 0.1W, 0603"
R16: "RES, 6.65 k, 0.1%, 0.1 W, 0603"
R18: "RES, 31.6 k, 0.1%, 0.1 W, 0603"
R19 R20: "RES, 10.2 k, 0.1%, 0.1 W, 0603"
R21: "RES, 2.2 k, 5%, 0.1 W, 0603"
R22: "RES, 1.5 M, 5%, 0.1 W, 0603"
R23: "RES, 215 k, 1%, 0.1 W, 0603"
R24: "RES, 3.30 k, 0.1%, 0.1 W, 0603"
R25: "RES, 100 k, 1%, 0.1 W, 0603"
R26: "RES, 357 k, 1%, 0.1 W, 0603"
R28: "RES, 1.0k ohm, 5%, 0.1W, 0603"
R29: "RES, 0.012, 1%, 0.5 W, 1206"
R30: "RES, 1.80 ohm, 1%, 0.25W, 1206"
R31: "RES, 121 k, 1%, 0.1 W, 0603"
R32: "RES, 51.1 k, 1%, 0.1 W, 0603"
R33: "RES, 49.9 ohm, 1%, 0.1W, 0603"
R34: "RES, 5.23 k, 1%, 0.1 W, 0603"
TP1 TP16: library part 5010, "Test Point, Multipurpose, Red, TH"
TP2: library part 5012, "Test Point, Multipurpose, White, TH"
TP3 TP5 TP6 TP7 TP8 TP9 TP10 TP11 TP12 TP13 TP14 TP15 TP17 TP18 TP19 TP22 TP25 TP27: library part 1503-2, "Terminal, Turret, TH, Double"
TP4: library part 5011, "Test Point, Multipurpose, Black, TH"
TP20 TP21: "Test Point, Multipurpose, Black, TH"
TP23 TP24: "Test Point, Miniature, Red, TH"
TP26 TP28 TP32: "Test Point, Miniature, Black, TH"
TP29 TP30: "Test Point, Miniature, White, TH"
TP31: "Test Point, Miniature, Orange, TH"
U1: library part LM53603PWP, "6th GENERATION BUCK REGULATOR, PWP0016H"
U2: "Synchronous Buck Regulator for 650mA Space Constraint Applications, DSX0010A"
U3 U4 U6 U7: "Low Dropout Voltage Tracking LDO, DBV0005A"
U5: "Dual 2.0A, High Frequency Synchronous Step-Down DC-DC Regulator, 16-pin LLP, Pb-Free"
U8: "300mA Low Dropout Voltage Tracking LDO, PWP0020D"
U9: "Automotive Catalog Low-Voltage Adjustable Precision Shunt Regulator, 80 mA, -40 to 125 degC, 3-pin SOT-23 (DBZ), Green (RoHS & no Sb/Br)"
U10: "4.5-V TO 52-V INPUT CURRENT MODE BOOST CONTROLLER, DGQ0010D"
ZZ1: library part AssemblyNoteLabel
ZZ2 ZZ3 ZZ4: library part AssemblyNote

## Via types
v1: diameter 22, hole 10, Top Layer to Bottom Layer, 60 vias
v2: diameter 20, hole 8, Top Layer to Bottom Layer, 29 vias

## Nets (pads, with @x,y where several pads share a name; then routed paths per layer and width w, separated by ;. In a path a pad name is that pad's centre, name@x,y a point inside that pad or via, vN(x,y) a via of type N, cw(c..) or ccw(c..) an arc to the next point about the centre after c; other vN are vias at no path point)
5V_1: C17.1 TP8.1 U3.4 | length 385
  Top Layer w20: TP8.1@1595,475 1770,475 1811.04,516.04 U3.4@1811.04,668.01
5V_2: C28.1 TP14.1 U7.4 | length 373.2
  Top Layer w20: TP14.1@3595,475 3765,475 3782.6,492.6 U7.4@3782.6,670.87
5V_3: C19.1 TP9.1 U4.4 | length 372.4
  Top Layer w20: TP9.1@2595,475 2765.2,475 2792.6,502.4 U4.4@2792.6,665.87
5V_4: C26.1 TP13.1 U6.4 | length 391.2
  Top Layer w20: TP13.1@4595,475 4785,475 4797.4,487.4 4797.6,487.4 U6.4@4797.6,670.87
5V_5: C36.1 TP19.1 U8.1 U8.10 | length 896.8
  Top Layer w17: v1(5691.14,693.86) U8.1@5744.84,693.86 5744.84,640.16 5775,610 5808.5,610 C36.1@5813.5,605 ; U8.10@5975.16,693.86 v1(6018.86,693.86)
  Top Layer w20: TP19.1@5595,475 5790,475 5813.5,498.5 C36.1@5813.5,605
  Bottom Layer w17: v1(5691.14,693.86) v1(6018.86,693.86)
6V: C12.1 C13.1 C16.1 C18.1 C25.1 C27.1 C35.1 L2.2 R9.2 TP6.1 U3.3 U4.3 U6.3 U7.3 U8.20 | length 6223
  Top Layer w17: C35.1@5743.5,1010 5743.06,1010 5743.06,958.66 5744.84,956.88 U8.20@5744.84,926.14
  Top Layer w20: C16.1@1773.5,840 1773.5,781.5 1775,780 1807.32,780 U3.3@1811.04,776.28 ; C16.1@1783.5,840 1783.5,965 2768.5,965 ; U4.3@2792.6,774.13 2792.6,787.4 2768.5,811.5 C18.1@2768.5,840 2768.5,965 ; U7.3@3782.6,779.13 3753.5,808.23 C27.1@3753.5,840 3753.5,965 ; v1(4665,1525) R9.2@4665,1575 ; U6.3@4797.6,779.13 4768.5,808.23 C25.1@4768.5,840 4768.5,965 ; TP6.1@5090,1190 5090,965 ; 5735,965 5090,965 ; 2768.5,965 3753.5,965 ; 3753.5,965 4768.5,965 ; 4768.5,965 5090,965
  Top Layer w30: L2.2@5084.96,1780 5084.96,1525.04 C12.1@5095,1515 5095,1195 TP6.1@5090,1190
  Bottom Layer w20: v1(4665,1525) 4673.87,1533.87 4906.96,1533.87 4909.81,1531.02 4948.98,1531.02 v1(5095,1385)
BAT+: C38.1 C39.1 C40.1 C42.1 L6.1 TP25.1
BAT-: C38.2 C39.2 C40.2 C42.2 L6.2 TP27.1
BIAS: C3.1 R1.1 U1.5 | length 214.8
  Top Layer w17: U1.5@6041.14,2982.8 6087.8,2982.8 6130,3025 R1.1@6173.5,3025 C3.1@6173.5,3090
FB: C11.2 R7.1 R8.2 U1.9 | length 224.7
  Top Layer w17: U1.9@5808.86,3059.57 5808.86,3119.65 R8.2@5798.5,3130 5795,3133.5 R7.1@5795,3203.5 C11.2@5870,3203.5
FB1: R9.1 R11.2 U2.4 | length 321.6
  Top Layer w9: v1(4835,1695) 4850.31,1679.68 U2.4@4850.31,1650.12
  Top Layer w15: R9.1@4665,1641.5 4669.87,1641.5 4726.37,1585 R11.2@4736.5,1585
  Top Layer w20: R11.2@4736.5,1585 v1(4778.54,1585)
  Bottom Layer w20: v1(4778.54,1585) 4778.54,1638.54 v1(4835,1695)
